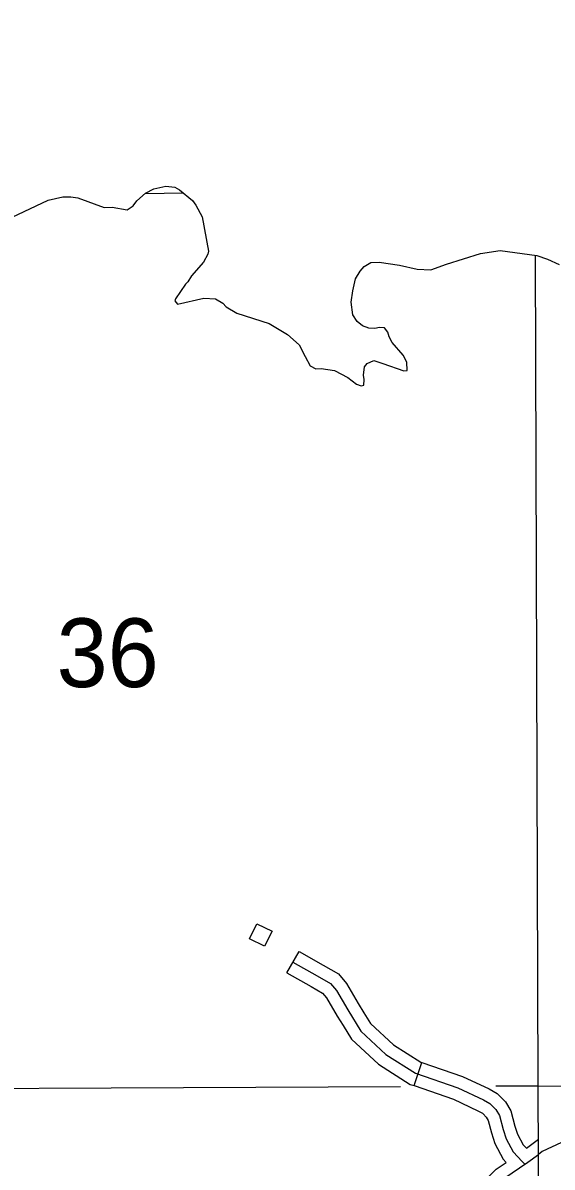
# Model space of a CAD drawing. Extents: x -19 to 366, y -4 to 359.
# Drawn here: x 138.792 to 139.408, y 197.944 to 199.276 of the extents above; entities that cross this region are included whole.
import ezdxf

# ---------------------------------------------------------------- set-up
doc = ezdxf.new("R2010")
doc.units = 0
for name, color, linetype in [('Level 4', 7, 'Continuous'), ('Level 45', 7, 'Continuous'), ('Level 5', 7, 'Continuous'), ('Level 56', 7, 'Continuous'), ('Level 60', 7, 'Continuous'), ('Level 63', 7, 'Continuous'), ('Level 9', 7, 'Continuous')]:
    doc.layers.add(name, color=color, linetype=linetype)

msp = doc.modelspace()

# ---------------------------------------------------------------- linework, layer by layer
at = {"layer": 'Level 4'}
for points in [[(139.3918, 198.0381), (139.3886, 199.0049)], [(139.2314, 198.0374), (138.3894, 198.0333), (138.3734, 198.0335), (137.3923, 198.046), (137.3636, 198.046), (136.3894, 198.0464), (136.3709, 198.0464), (135.3908, 198.0464), (135.3637, 198.047), (134.4615, 198.0663), (134.4184, 198.067), (133.4674, 198.0826)], [(139.3918, 198.0381), (139.3425, 198.0379)]]:
    msp.add_lwpolyline(points, dxfattribs=at)
at = {"layer": 'Level 45'}
for p, q in [((139.0993, 198.1701), (139.1134, 198.1948)), ((139.2474, 198.0387), (139.2566, 198.0656))]:
    msp.add_line(p, q, dxfattribs=at)
for points in [[(139.1134, 198.1948), (139.1415, 198.1789), (139.1593, 198.1687), (139.1687, 198.1575), (139.1824, 198.1342), (139.189, 198.1234)], [(139.1063, 198.1825), (139.1344, 198.1665), (139.1501, 198.1576), (139.1571, 198.1493), (139.1702, 198.1269), (139.1855, 198.102), (139.2146, 198.0748), (139.249, 198.0531), (139.2985, 198.0362), (139.3282, 198.0221), (139.3355, 198.018), (139.3426, 198.011), (139.3467, 198.0039), (139.3512, 197.9876), (139.3547, 197.9768), (139.3627, 197.9615), (139.3732, 197.9503), (139.3767, 197.9468)], [(139.0993, 198.1701), (139.1274, 198.1542), (139.1408, 198.1465), (139.1455, 198.141), (139.158, 198.1196), (139.1648, 198.1085)], [(139.189, 198.1234), (139.1966, 198.1111), (139.2233, 198.0861), (139.2552, 198.066), (139.2566, 198.0656)], [(139.1648, 198.1085), (139.1744, 198.0929), (139.2058, 198.0635), (139.2429, 198.0402), (139.2474, 198.0387)], [(139.2566, 198.0656), (139.3039, 198.0494), (139.3348, 198.0348), (139.3442, 198.0294), (139.3523, 198.0213)], [(139.2474, 198.0387), (139.2932, 198.023), (139.3217, 198.0095), (139.3269, 198.0066), (139.3322, 198.0012)], [(139.6628, 198.0385), (139.6544, 198.0339), (139.6009, 198.013), (139.5561, 197.997), (139.5261, 197.9921), (139.4882, 197.9879), (139.4662, 197.9845), (139.4407, 197.9784), (139.4191, 197.9727), (139.3967, 197.9621), (139.3922, 197.9587)], [(139.3523, 198.0213), (139.3539, 198.0197), (139.3599, 198.0095), (139.3648, 197.9917), (139.3679, 197.9823), (139.3744, 197.9698), (139.3781, 197.9659)], [(139.3313, 198.0022), (139.3335, 197.9983), (139.3376, 197.9836), (139.3416, 197.9713), (139.351, 197.9531), (139.3545, 197.9494)], [(139.3781, 197.9659), (139.3921, 197.9764)], [(139.3519, 197.9306), (139.38, 197.9496), (139.3922, 197.9587)], [(139.3137, 197.9117), (139.3162, 197.9149), (139.3428, 197.9416), (139.3545, 197.9494)]]:
    msp.add_lwpolyline(points, dxfattribs=at)
at = {"layer": 'Level 5'}
msp.add_lwpolyline([(138.9341, 199.0769), (138.9787, 199.0776)], dxfattribs=at)
at = {"layer": 'Level 56'}
msp.add_lwpolyline([(139.082, 198.2186), (139.0734, 198.2009), (139.0556, 198.2095), (139.0642, 198.2272)], close=True, dxfattribs=at)
at = {"layer": 'Level 60'}
for points in [[(146.7783, 1.697), (146.5788, 10.3131), (146.3785, 18.9294), (146.1776, 27.5458), (145.9759, 36.1624), (145.7736, 44.7791), (145.5705, 53.396), (145.3668, 62.013), (145.1624, 70.6301), (144.9572, 79.2474), (144.7514, 87.8648), (144.5449, 96.4823), (144.3377, 105.1), (144.1299, 113.7179), (143.9213, 122.3359), (143.712, 130.954), (143.5021, 139.5723), (143.2915, 148.1907), (143.0802, 156.8092), (142.8682, 165.4279), (142.6555, 174.0468), (142.4422, 182.6658), (142.2282, 191.2849), (142.0135, 199.9042), (141.7981, 208.5236), (141.582, 217.1432), (141.3653, 225.7629), (141.1479, 234.3828), (140.9298, 243.0028), (140.711, 251.623), (140.4916, 260.2433), (140.2715, 268.8638), (140.0508, 277.4844), (139.8293, 286.1051), (139.6072, 294.726), (139.3845, 303.3471), (139.161, 311.9683), (138.937, 320.5896), (138.7122, 329.2111), (138.4868, 337.8328), (138.2607, 346.4546)], [(139.4406, 1.5315), (139.2511, 10.1473), (139.0608, 18.7633), (138.8699, 27.3793), (138.6784, 35.9956), (138.4861, 44.6119), (138.2932, 53.2285), (138.0997, 61.8451), (137.9055, 70.4619), (137.7106, 79.0789), (137.5151, 87.6959), (137.319, 96.3132), (137.1221, 104.9306), (136.9247, 113.5481), (136.7265, 122.1658), (136.5278, 130.7836), (136.3283, 139.4016), (136.1282, 148.0197), (135.9275, 156.6379), (135.7261, 165.2564), (135.5241, 173.8749), (135.3214, 182.4936), (135.1181, 191.1125), (134.9141, 199.7315), (134.7095, 208.3506), (134.5043, 216.9699), (134.2984, 225.5894), (134.0919, 234.209), (133.8847, 242.8288), (133.6769, 251.4487), (133.4685, 260.0687), (133.2594, 268.6889), (133.0497, 277.3093), (132.8393, 285.9298), (132.6283, 294.5504), (132.4167, 303.1713), (132.2044, 311.7922), (131.9916, 320.4133), (131.778, 329.0346), (131.5639, 337.656), (131.3491, 346.2776)], [(0, 198.1326), (7.1014, 198.137), (14.2028, 198.1503), (21.3042, 198.1724), (28.4055, 198.2034), (35.5068, 198.2433), (42.6081, 198.292), (49.7092, 198.3496), (56.8103, 198.4161), (63.9113, 198.4913), (71.0123, 198.5755), (78.1131, 198.6685), (85.2137, 198.7704), (92.3143, 198.8811), (99.4147, 199.0007), (106.5149, 199.1291), (113.615, 199.2664), (120.7149, 199.4126), (127.8146, 199.5676), (134.9141, 199.7315), (142.0135, 199.9042), (149.1125, 200.0858), (156.2114, 200.2762), (163.31, 200.4755), (170.4084, 200.6837), (177.5065, 200.9007), (184.6043, 201.1265), (191.7018, 201.3612), (198.799, 201.6048), (205.896, 201.8572), (212.9926, 202.1185), (220.0888, 202.3886), (227.1848, 202.6676), (234.2803, 202.9554), (241.3755, 203.2521), (248.4704, 203.5576), (255.5648, 203.872), (262.6589, 204.1952), (269.7525, 204.5273), (276.8457, 204.8682), (283.9385, 205.218), (291.0309, 205.5766), (298.1228, 205.9441), (305.2142, 206.3204), (312.3051, 206.7056), (319.3956, 207.0996), (326.4856, 207.5024), (333.5751, 207.9141), (340.664, 208.3347)], [(0, 189.5162), (7.1121, 189.5206), (14.2243, 189.5339), (21.3364, 189.556), (28.4484, 189.5869), (35.5605, 189.6267), (42.6725, 189.6754), (49.7844, 189.7329), (56.8962, 189.7992), (64.0079, 189.8744), (71.1196, 189.9584), (78.2311, 190.0512), (85.3425, 190.1529), (92.4538, 190.2635), (99.5649, 190.3829), (106.6759, 190.5111), (113.7867, 190.6482), (120.8974, 190.7941), (128.0078, 190.9489), (135.1181, 191.1125), (142.2282, 191.2849), (149.338, 191.4662), (156.4476, 191.6563), (163.5569, 191.8553), (170.666, 192.0631), (177.7749, 192.2798), (184.8835, 192.5053), (191.9917, 192.7396), (199.0997, 192.9828), (206.2074, 193.2348), (213.3147, 193.4956), (220.4218, 193.7653), (227.5285, 194.0438), (234.6348, 194.3312), (241.7408, 194.6274), (248.8464, 194.9324), (255.9516, 195.2463), (263.0564, 195.569), (270.1608, 195.9005), (277.2648, 196.2409), (284.3683, 196.5901), (291.4715, 196.9481), (298.5741, 197.315), (305.6763, 197.6907), (312.7781, 198.0753), (319.8793, 198.4686), (326.9801, 198.8708), (334.0804, 199.2818), (341.1801, 199.7017)]]:
    msp.add_spline(points, degree=3, dxfattribs=at)
at = {"layer": 'Level 63'}
for points in [[(139.3918, 198.0381), (139.65, 198.0385)], [(139.3969, 192.5514), (139.3992, 193.0141), (139.3992, 193.0186), (139.4031, 194.0054), (139.4028, 194.0236), (139.4049, 195.0052), (139.4049, 195.018), (139.4015, 196.0081), (139.4014, 196.0267), (139.3967, 197.0057), (139.3967, 197.0165), (139.3918, 198.0381)]]:
    msp.add_lwpolyline(points, dxfattribs=at)
at = {"layer": 'Level 9'}
for points in [[(138.7796, 199.0494), (138.8212, 199.0693), (138.8385, 199.0731), (138.8476, 199.0732), (138.8559, 199.0721), (138.8866, 199.0608), (138.8957, 199.0612), (138.9135, 199.0579), (138.9203, 199.0628), (138.9244, 199.0685), (138.9346, 199.0773), (138.9444, 199.0823), (138.9583, 199.0854), (138.9689, 199.0843), (138.9742, 199.0813), (138.9894, 199.0688), (138.9932, 199.0635), (139.0005, 199.0499), (139.0082, 199.0097), (139.0071, 199.0063), (139.0022, 198.9971), (138.9883, 198.9811), (138.9841, 198.9743), (138.9811, 198.9713), (138.9695, 198.9545), (138.9687, 198.9519), (138.9718, 198.9481), (139.0024, 198.955), (139.016, 198.9543), (139.0247, 198.9494), (139.0285, 198.9449), (139.041, 198.9377), (139.0785, 198.9257), (139.1001, 198.9129), (139.1134, 198.9008), (139.1206, 198.8872), (139.1264, 198.8766), (139.1328, 198.8728), (139.1392, 198.8732), (139.1547, 198.871), (139.1703, 198.8627), (139.1805, 198.8552)], [(139.1805, 198.8552), (139.1858, 198.8533), (139.1888, 198.8541), (139.1892, 198.8605), (139.1884, 198.8654), (139.1895, 198.8753), (139.1929, 198.8791), (139.2004, 198.8826), (139.211, 198.8792), (139.2353, 198.8706), (139.2394, 198.871), (139.239, 198.8808), (139.2348, 198.8888), (139.2219, 198.9035), (139.2185, 198.9103), (139.2169, 198.9156), (139.2128, 198.9205), (139.2071, 198.9209), (139.2018, 198.9197), (139.1946, 198.9201), (139.1874, 198.9231), (139.181, 198.928), (139.176, 198.9356), (139.1741, 198.9504), (139.1759, 198.9637), (139.1792, 198.9777), (139.1845, 198.9864), (139.1894, 198.9922), (139.1969, 198.9967), (139.2068, 198.9972), (139.2306, 198.9935), (139.251, 198.989), (139.2669, 198.9883), (139.285, 198.9948), (139.3247, 199.0071), (139.3477, 199.0106), (139.3905, 199.0047), (139.4026, 199.0006), (139.4163, 198.9942)]]:
    msp.add_lwpolyline(points, dxfattribs=at)

# ---------------------------------------------------------------- texts
at = {"layer": 'Level 5'}
msp.add_text('36', height=0.08, dxfattribs=at).set_placement((138.8311, 198.5025))

doc.saveas('drawing.dxf')
